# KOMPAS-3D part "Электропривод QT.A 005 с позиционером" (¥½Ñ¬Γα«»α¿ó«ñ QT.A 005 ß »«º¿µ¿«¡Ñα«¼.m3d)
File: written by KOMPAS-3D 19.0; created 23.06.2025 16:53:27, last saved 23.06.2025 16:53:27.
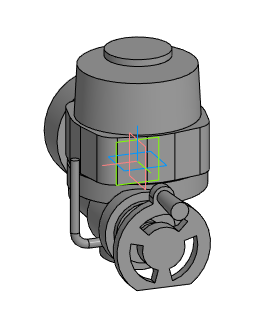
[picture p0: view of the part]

Document properties: Автор: Евгений; Полное имя файла: E:\Dendor Работа Сачек\3D для проектировщиков\3.5 Тип QT.А Электропривод\stp_Электропривод QT.A с позиционером\Электропривод QT.A 005 с позиционером.m3d

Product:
- Part/product: Электропривод QT.A 005 с позиционером

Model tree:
1. Операция без истории:1  (labels: Электропривод QT.A 005 с позиционером)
